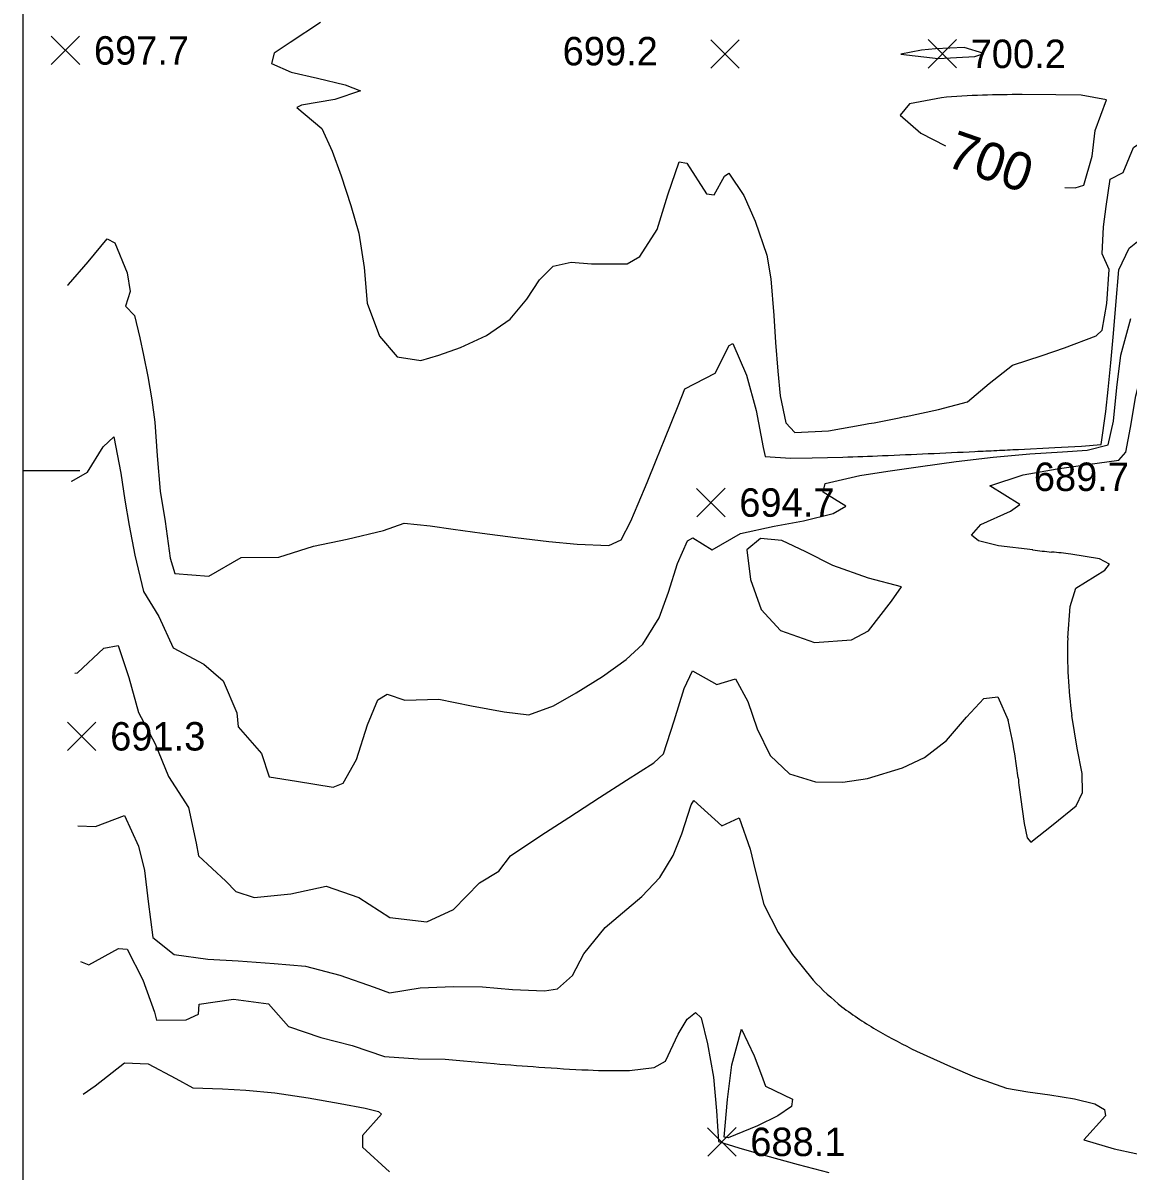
# Model space of a CAD drawing. Extents: x 2566079 to 2571326, y 424054 to 426896.
# Drawn here: x 2566079 to 2566662, y 425631 to 426236 of the extents above; entities that cross this region are included whole.
import ezdxf

# ---------------------------------------------------------------- set-up
doc = ezdxf.new("R2010")
doc.units = 0
for name, color, linetype in [('Contour_ADS_Label_Major', 7, 'Continuous'), ('Contour_ADS_Major', 7, 'Continuous'), ('Contour_ADS_Minor', 7, 'Continuous'), ('Contour_ADS_Spot_Elevation', 7, 'Continuous'), ('Contour_ADS_State_Plane_Border', 7, 'Continuous')]:
    doc.layers.add(name, color=color, linetype=linetype)

# ---------------------------------------------------------------- blocks, each defined once
blk = doc.blocks.new('S750')
at = {"layer": 'Contour_ADS_Spot_Elevation'}
for p, q in [((-0.5, 0.498), (0.5, -0.498)), ((-0.498, -0.5), (0.498, 0.5))]:
    blk.add_line(p, q, dxfattribs=at)

msp = doc.modelspace()

# ---------------------------------------------------------------- linework, layer by layer
at = {"layer": 'Contour_ADS_Major'}
msp.add_lwpolyline([(2566553.23, 426221.58), (2566542.32, 426219.5), (2566562.1, 426217.32), (2566581.33, 426218.36), (2566586.21, 426219.94), (2566575.77, 426222.99), (2566560.66, 426222.36), (2566553.23, 426221.58)], close=True, dxfattribs=at)
for points in [[(2566563.76, 426196.58), (2566547.01, 426193.44), (2566541.98, 426187.36), (2566552.9, 426177.89), (2566565.98, 426171.19)], [(2566628.96, 426149.31), (2566634.29, 426149.13), (2566638.83, 426150.45), (2566643.29, 426165.71), (2566644.92, 426179.34), (2566650.9, 426195.47), (2566637.55, 426197.98), (2566624.12, 426198.18), (2566606.34, 426198.25)], [(2566108.35, 425812.75), (2566117.59, 425812.29), (2566132.96, 425818.14), (2566140.25, 425802.02), (2566143.49, 425789.22), (2566145.3, 425772.84), (2566147.89, 425753.81), (2566159.15, 425744.9), (2566176.83, 425742.44), (2566192.92, 425741.43), (2566211.88, 425740.12), (2566228.31, 425738.64), (2566246.45, 425734.04), (2566264.5, 425727.64), (2566272.61, 425724.61), (2566288.89, 425727.29), (2566306.43, 425727.92), (2566321.78, 425727.79), (2566337.51, 425726.41), (2566354.45, 425725.67), (2566361.34, 425726.81), (2566369.25, 425733.78), (2566375.15, 425745.17), (2566386.38, 425759.1), (2566395.59, 425766.83), (2566405.85, 425775.46), (2566415.22, 425785.51), (2566422.21, 425797.05), (2566426.92, 425808.53), (2566431.73, 425823.75), (2566433.25, 425826.08), (2566448.01, 425812.67), (2566457.18, 425816.84), (2566462.93, 425800.38), (2566465.47, 425789.27), (2566470.2, 425771.28), (2566477.68, 425756.39), (2566485.18, 425744.92), (2566496.21, 425731.28)], [(2566550.65, 425693.94), (2566568.5, 425685.76), (2566581.26, 425680.38), (2566598.08, 425674.36), (2566609.39, 425672.46), (2566620.97, 425670.92), (2566634.05, 425668.83), (2566644.64, 425666.21), (2566649.77, 425663.14), (2566650.37, 425659.79), (2566638.84, 425647.23), (2566654.95, 425642.36), (2566666.37, 425639.9), (2566681.19, 425637.14), (2566697.58, 425634.46), (2566713.29, 425632.28), (2566726.44, 425630.92), (2566744.39, 425629.75)]]:
    msp.add_lwpolyline(points, dxfattribs=at)
for centre, radius, start, end in [((2566594.73, 425858.61), 339.38, 91.56196, 95.23591), ((2566608.58, 425502.39), 695.86, 90.18466, 91.90259), ((2566594.55, 425822.55), 134.17, 222.86411, 231.66362), ((2566621.51, 425862.35), 182.14, 232.77843, 239.99394), ((2566681.81, 425966.88), 302.81, 240.00441, 244.33386)]:
    msp.add_arc(centre, radius, start, end, dxfattribs=at)
at = {"layer": 'Contour_ADS_Minor'}
for points in [[(2566236.33, 426236.22), (2566220.25, 426225.74), (2566211.82, 426220.14), (2566210.39, 426214.62), (2566220.87, 426210.08), (2566234.73, 426206.91), (2566249.22, 426203.46), (2566257.3, 426200.23), (2566243.92, 426195.62), (2566226.21, 426192.73), (2566223.86, 426191.41), (2566236.91, 426180.42), (2566242.44, 426168.48), (2566247.11, 426155.41), (2566252.26, 426139.82), (2566256.46, 426125.25), (2566259.32, 426107.06), (2566260.94, 426088.24), (2566267.46, 426070.94), (2566276.71, 426060.05), (2566289.14, 426058.07), (2566298.67, 426060.89), (2566310.14, 426064.95), (2566323.87, 426071.18), (2566336.36, 426079.75), (2566345.13, 426090.32), (2566351.78, 426100.58), (2566358.92, 426107.71), (2566368.44, 426109.84), (2566379.27, 426108.93), (2566398.09, 426109.07), (2566404.67, 426112.83), (2566413.81, 426127.13), (2566419.55, 426145.35), (2566425.51, 426162.78), (2566429.44, 426162.13), (2566439.81, 426145.94), (2566443.84, 426145.46), (2566449.45, 426155.22), (2566451.65, 426156.77), (2566459.63, 426145.06), (2566465.5, 426131.54), (2566471.67, 426113.5), (2566473.74, 426101.12), (2566475.32, 426081.73), (2566476.29, 426067.55), (2566477.42, 426052.48), (2566478.69, 426039.4), (2566481.71, 426025.13), (2566486.49, 426020.13), (2566504.16, 426020.94), (2566522.92, 426024.22)], [(2566544.25, 426028.42), (2566562.27, 426032.19), (2566577.53, 426036.32), (2566589, 426045.91), (2566601.29, 426055.53), (2566616.86, 426060.71), (2566628.65, 426064.67), (2566645.38, 426070.99), (2566648.55, 426074.11), (2566651.09, 426088.01), (2566652.22, 426106), (2566648.52, 426114.26), (2566649.21, 426128.46), (2566650.62, 426139.3), (2566652.8, 426153.69), (2566659.61, 426157.16), (2566665.06, 426170.42), (2566670.11, 426173.74), (2566689.86, 426173.34), (2566695.72, 426164.58), (2566706.43, 426160.6), (2566723.04, 426161.24)], [(2566604.39, 426011.19), (2566623.68, 426012.18), (2566637.64, 426012.92), (2566648.09, 426013.68), (2566650.57, 426031.19), (2566651.81, 426042.71), (2566653.18, 426056.72), (2566654.54, 426072.32), (2566655.76, 426087.28), (2566657.32, 426105.86), (2566662.87, 426117.32), (2566667.28, 426120.72), (2566679.3, 426122.41), (2566690.95, 426119.07), (2566706.14, 426107.46), (2566713.03, 426106.95), (2566722.27, 426116.69), (2566731.49, 426127.75), (2566747.74, 426139.36)], [(2566102.77, 426097.69), (2566103.34, 426098.12), (2566113.68, 426110.04), (2566123.83, 426122.22), (2566127.78, 426120.13), (2566134.27, 426104.18), (2566135.89, 426094.5), (2566133.47, 426086.75), (2566138.1, 426081.78), (2566140.9, 426070.01), (2566142.88, 426060.88), (2566145.22, 426049.56), (2566147.34, 426037.37), (2566148.82, 426025.59), (2566150.19, 426007.82), (2566151.78, 425989.18), (2566154.43, 425973.15), (2566157.01, 425953.77), (2566159.51, 425945.8), (2566177.45, 425944.36), (2566194.41, 425954.21), (2566214.35, 425954.36), (2566232.51, 425960.17), (2566250.42, 425963.92), (2566269.45, 425968.41), (2566280.43, 425972.26), (2566294.06, 425970.85), (2566306.24, 425969.08), (2566321.54, 425966.93), (2566339.13, 425964.67), (2566356.73, 425962.63), (2566371.69, 425961.12), (2566388.43, 425960.57), (2566394.95, 425963.51), (2566400.05, 425973.3), (2566403.92, 425982.49), (2566408.54, 425993.69), (2566413.39, 426005.52), (2566417.95, 426016.73), (2566424.87, 426034.07), (2566428.37, 426043.01), (2566444.41, 426051.38), (2566451.83, 426065.9), (2566453.69, 426066.99), (2566461, 426050.22), (2566466.14, 426031.67), (2566469.74, 426012.13), (2566470.86, 426007.42), (2566484.27, 426006.56), (2566495.63, 426006.69), (2566511.73, 426007.11)], [(2566104.79, 425994.61), (2566105.18, 425994.38), (2566113.38, 425999.14), (2566121.56, 426012.6), (2566127.31, 426017.73), (2566130.95, 425998.68), (2566133.08, 425984.47), (2566135.35, 425970.96), (2566138.42, 425955.34), (2566142.94, 425936.22), (2566150.93, 425923.05), (2566158.53, 425906.61), (2566174.67, 425897.9), (2566184.96, 425889.11), (2566192.21, 425872.21), (2566192.82, 425864.96), (2566205.17, 425850.91), (2566209.18, 425838.58), (2566223.61, 425836.23), (2566242.96, 425833.04), (2566248.26, 425835.15), (2566255.21, 425847.75), (2566261.06, 425865.92), (2566266.54, 425879.05), (2566271.41, 425882.14), (2566280.76, 425878.88), (2566298.74, 425879.52), (2566315.92, 425875.99), (2566333.24, 425872.86), (2566346.12, 425871.27), (2566359.1, 425876.03), (2566371.1, 425882.79), (2566385.03, 425891.46), (2566397.59, 425900.45), (2566406.23, 425908.48), (2566414.93, 425922.35), (2566419.85, 425935.88), (2566424.58, 425951.04), (2566429.9, 425962.89), (2566432.59, 425964.45), (2566442.94, 425958.24), (2566457.75, 425966.84), (2566475.54, 425970.65), (2566491.05, 425973.51), (2566506.64, 425977.41), (2566513.32, 425981.21), (2566501.48, 425988.56), (2566502.49, 425993.16), (2566520.79, 425997.39), (2566535.46, 425999.67), (2566552.68, 426002.22), (2566571.54, 426004.81), (2566591.15, 426007.08), (2566610.43, 426008.77), (2566627.57, 426009.96), (2566640.61, 426010.77), (2566651.81, 426013.54), (2566654.52, 426026.11), (2566656.38, 426043.8), (2566658.45, 426060.92), (2566663.73, 426080.17)], [(2566611.92, 425958.13), (2566593.92, 425960.38), (2566583.4, 425963), (2566579.74, 425965.88), (2566584.63, 425971.6), (2566600.29, 425978.54), (2566605.21, 425982.16), (2566589.41, 425992.02), (2566606.97, 425997.81), (2566624.76, 426000.85), (2566640.81, 426003.23), (2566657.32, 426005.49), (2566661.02, 426009.78), (2566663.47, 426022.69), (2566666.32, 426039.45), (2566667.36, 426043.53), (2566679.95, 426034.08), (2566689.66, 426039.06), (2566708.36, 426035.52), (2566719.59, 426034.73), (2566734.46, 426033.75)], [(2566630.4, 425911.82), (2566631.71, 425928.32), (2566634.62, 425937.92), (2566650.05, 425947.57), (2566652.38, 425950.63), (2566647.14, 425953.55), (2566631.97, 425955.97)], [(2566106.78, 425893.1), (2566108.16, 425893.32), (2566121.97, 425906.3), (2566129.47, 425907.79), (2566135.12, 425890.94), (2566140.28, 425872.42), (2566149.05, 425855.98), (2566156.17, 425838.64), (2566166.68, 425822.44), (2566170.75, 425803.54), (2566171.93, 425796.9), (2566186.36, 425783.44), (2566191.66, 425778.06), (2566201.3, 425774.89), (2566220.58, 425776.9), (2566239.22, 425780.81), (2566256.42, 425774.93), (2566272.9, 425764.43), (2566292.4, 425762.16), (2566306.49, 425768.61), (2566320.2, 425782.68), (2566330.37, 425788.84), (2566336.41, 425796.94), (2566352.54, 425807.59), (2566367.19, 425817.06), (2566383.48, 425827.59), (2566397.69, 425836.75), (2566412.17, 425845.99), (2566417.28, 425850.66), (2566422.78, 425868.03), (2566428.01, 425885.05), (2566432.51, 425894.41), (2566445.34, 425887.15), (2566455.13, 425890.16), (2566461.68, 425878.18), (2566466.62, 425863.88), (2566473.43, 425849.82), (2566483.73, 425840.17), (2566497.32, 425835.9), (2566511.73, 425835.72), (2566524.88, 425837.72), (2566543.29, 425843.21), (2566554.88, 425848.79), (2566566.51, 425857.75), (2566577.07, 425869.91), (2566586.15, 425879.83), (2566593.5, 425880.76), (2566598.98, 425868.39)], [(2566605.54, 425827.86), (2566607.43, 425813.89), (2566609.06, 425806.4), (2566611.02, 425804), (2566622.8, 425813.48), (2566634.78, 425823.17), (2566638.2, 425830.25), (2566638, 425840.27), (2566635.46, 425853.68), (2566632.49, 425870.83)], [(2566109.75, 425741.16), (2566114.04, 425739.45), (2566129.71, 425747.96), (2566134.31, 425747.68), (2566142.48, 425731.53), (2566148.69, 425714.4), (2566149.84, 425710.32), (2566165.49, 425710.48), (2566172.01, 425713.41), (2566172.21, 425718.67), (2566190.33, 425721.24), (2566208.84, 425718.93), (2566219.32, 425706.83), (2566236.45, 425701.15), (2566252.98, 425696.88), (2566270.09, 425691.1), (2566287.81, 425689.81), (2566302.03, 425689.6), (2566311.78, 425688.75), (2566327.87, 425687.35)], [(2566399.33, 425683.69), (2566412.29, 425685.35), (2566418.2, 425688.64), (2566424.9, 425702.88), (2566429.62, 425710.84), (2566433.99, 425714.36), (2566437.14, 425711.54), (2566440.44, 425697.79), (2566443.51, 425680.23), (2566445.13, 425662.42), (2566446.25, 425646.18), (2566456.99, 425642.92), (2566471.06, 425638.94), (2566488.26, 425634.15), (2566504.32, 425629.84)], [(2566111.11, 425671.26), (2566117.34, 425675.7), (2566132.82, 425687.73), (2566145.36, 425687.13), (2566159.95, 425679.48), (2566168.91, 425674.64), (2566184.62, 425673.99), (2566196.85, 425673.39), (2566212.19, 425671.93), (2566229.7, 425669.37), (2566246.65, 425666.37), (2566259.83, 425663.77), (2566266.85, 425662.12), (2566268.48, 425660.71), (2566258.46, 425649.51), (2566258.5, 425643.29), (2566272.61, 425630.24)]]:
    msp.add_lwpolyline(points, dxfattribs=at)
for points in [[(2566478.94, 425915.75), (2566496.88, 425909.42), (2566516.33, 425910.79), (2566525.33, 425915.57), (2566537.53, 425931.18), (2566542.81, 425938.75), (2566525.31, 425943.28), (2566506.52, 425949.91), (2566492.21, 425957.19), (2566479.62, 425963.1), (2566468.32, 425964.27), (2566461.12, 425958.29), (2566463.13, 425942.64), (2566468.66, 425926.74), (2566478.94, 425915.75)], [(2566468.82, 425681.23), (2566471, 425675.42), (2566485.24, 425668.52), (2566484.68, 425664.73), (2566477.49, 425659.76), (2566466.75, 425654.57), (2566451.22, 425648.26), (2566449.19, 425648.54), (2566450.89, 425668.45), (2566453.23, 425686.62), (2566458.31, 425705.49), (2566464.95, 425691.49), (2566468.82, 425681.23)]]:
    msp.add_lwpolyline(points, close=True, dxfattribs=at)
for centre, radius, start, end in [((2566275.54, 427336.82), 1335.7, 280.67309, 281.60564), ((2566421.32, 428730.06), 2724.45, 271.90172, 272.3445), ((2566323.2, 431186.97), 5183.32, 272.31714, 272.58345), ((2566203.85, 433839.86), 7838.89, 272.580908, 272.761275), ((2566145.57, 435040.32), 9040.76, 272.763683, 272.836333), ((2566085.84, 436496.26), 10497.88, 272.768725, 272.831292), ((2566733.81, 427042), 1090.7, 263.58345, 264.11286), ((2566589.9, 425612.42), 346.11, 83.01923, 84.68926), ((2566867.66, 425904.81), 237.37, 178.30739, 183.25766), ((2566882.1, 425903.2), 251.7, 182.70635, 187.38997), ((2566390.98, 425818.05), 214, 8.07897, 13.60396), ((2566253.9, 425796.82), 352.71, 6.70539, 8.36533), ((2572445.88, 426604.82), 5891.8, 187.478278, 187.577744), ((2566484.17, 427536.87), 1856.11, 265.16961, 265.89909), ((2566417.72, 426584.47), 901.4, 265.78249, 267.43808), ((2566392.51, 426006.5), 322.88, 267.32386, 271.21112)]:
    msp.add_arc(centre, radius, start, end, dxfattribs=at)
at = {"layer": 'Contour_ADS_State_Plane_Border'}
msp.add_line((2566079.33, 426000), (2566109.33, 426000), dxfattribs=at)
msp.add_lwpolyline([(2566079.33, 424077.11), (2571302.93, 424077.11), (2571302.93, 426873.74), (2566079.33, 426873.74), (2566079.33, 424077.11)], close=True, dxfattribs=at)

# ---------------------------------------------------------------- block references
at = {"layer": 'Contour_ADS_Spot_Elevation', "xscale": 15, "yscale": 15}
for p in [(2566101.76, 426221.52), (2566449.62, 426219.61), (2566564.23, 426219.73), (2566442.18, 425983.14), (2566110.33, 425859.9), (2566447.97, 425646.08)]:
    msp.add_blockref('S750', p, dxfattribs=at)

# ---------------------------------------------------------------- texts
at = {"layer": 'Contour_ADS_Label_Major'}
msp.add_text('700', height=20, rotation=340.842, dxfattribs=at).set_placement((2566565.36, 426160.82))
at = {"layer": 'Contour_ADS_Spot_Elevation'}
for s, p in [('697.7', (2566116.76, 426214.02)), ('699.2', (2566364, 426213.63)), ('700.2', (2566579.23, 426212.23)), ('689.7', (2566612.55, 425989.23)), ('694.7', (2566457.18, 425975.64)), ('691.3', (2566125.33, 425852.4)), ('688.1', (2566462.97, 425638.58))]:
    msp.add_text(s, height=15, dxfattribs=at).set_placement(p)

doc.saveas('drawing.dxf')
